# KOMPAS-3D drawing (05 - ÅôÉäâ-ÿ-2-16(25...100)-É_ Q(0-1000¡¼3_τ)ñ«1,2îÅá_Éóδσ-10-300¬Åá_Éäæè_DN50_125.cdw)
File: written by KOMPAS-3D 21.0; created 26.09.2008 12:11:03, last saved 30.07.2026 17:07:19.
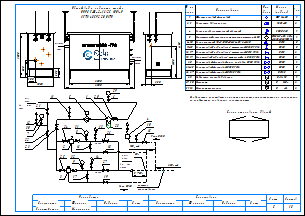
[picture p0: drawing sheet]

Sheets 1-2: A3, landscape

Document properties: Наименование: Макро:21; Автор: RaskoAdmin; Форматы листов документа: 2xA3; Полное имя файла: \\ur38nt01\Departments\КТО\КБ ПУРДГ\Заявки\Прайс-лист на типовые шкафы ГРПШ\ПУРДГ_стандарт_30_04_2026\ПУРДГ с РДСК\ПУРДГ-Ш-2-16(25...100)-Р_ Q(0-1000нм3_ч)до1,2МПа_Рвых-10-300кПа_РДСК_DN50_125.cdw

Title block, sheet 1: Наименование: Пункт учета газа / ПУГ-Ш-400-Р / ЛГТИ.485922.001ТУ; designation: ЛГТИ.03.4411141; sheet number: 1; Количество листов документа: 2; organisation: ООО "ЭЛЬСТЕР Газэлектроника"; Форматы листов документа: A3; stored path: C:\Рабочие документы\Компас\ПУГ\Схема.cdw; Разработал: Устинов; Проверил: Кошкин; Утвердил: Кошкин
Title block, sheet 2: sheet number: 2; stored path: D:\Рабочие документы\Заявки\ПУРДГ\ПУРДГ-ШУЭО-2-100-Р 4411220.cdw; designation, second copy: ЛГТИ.03.4411141-

Views: Вид 1, Вид 2
Referenced files: wcvoit.frw
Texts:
  Normal
  № на
  схеме
  Усл.
  обозн.
  Марка
  (модель)
  Кол.
  Фильтр газовый фланцевый
  ФГ 16-50
  Регулятор давления газа
  РДСК-50
  Клапан предохранительный сбросной
  КПС DN20
  Измерительный комплекс с ротационным счетчиком Ду50
  СГ-ЭК-Р-(0,2...2,0)-
  Кран кнопочный VE-РАСКО-НЗ-1,6-G1/2-М20
  DN15
  Кран шаровой "под приварку" штуцерный DN20 PN16
  DN20
  Кран шаровой "под приварку" штуцерный DN15 PN16
  Кран шаровой "под приварку" штуцерный п/п DN20 PN16
  Кран шаровой фланцевый с мех. приводом DN50 PN16
  Кран шаровой фланцевый DN50 PN16
  Кран шаровой фланцевый DN125 PN16
  DN50
  DN125
  Индикатор перепада давления
  Манометр
  Манометр-напоромер
  Delta 15
  0...     МПа
  0...     кПа
  Общий вид и габариты шкафа
  ПУРДГ-Ш-2-16(25...100)-Р
  Выход газа
  Вход газа
  logo-rasko-ge.png
  DN 1
  местное
  сопротивление
  Римп DN20
  Выход
  газа
  Р=     кПа
  Вход
  Р=       МПа
  PDI
  Схема открывания дверей
  Предприятие изготовитель может заменять комплектующие на аналогичные,
  не ухудшающие заявленных характеристик.
  Должность
  Конструктор
  Фамилия
  Подпись
  Дата
  Согласовано
  Максимкин
  Лист
  Листов
  POLYLINE_STYLE_0.18_RGB_0_0_0
  POLYLINE_STYLE_0.50_RGB_0_0_0
  POLYLINE_STYLE_0.34_RGB_0_0_0
  PHANTOM_RGB_0_0_0_SC_1_THICK_0.18
  K5LT_THIN_RGB_0_0_0_THICK_0.18
  K5LT32769_RGB_0_0_0_THICK_0.18
  K5LT12_RGB_0_0_0_SC_1_THICK_0.18
  K5LT_DASHED_RGB_0_0_0_SC_1_THICK_0.18
  ACISOTGL_RGB_0_0_0_SC_0.8_THICK_0.25
  CONTINUOUS_RGB_0_127_31_THICK_0.3
  CONTINUOUS_RGB_0_0_255_THICK_0.35
  CONTINUOUS_RGB_255_0_0_THICK_0.35
  POLYLINE_STYLE_0.25_RGB_0_0_0
  CONTINUOUS_RGB_0_0_0_THICK_0.5
  POLYLINE_STYLE_0.35_RGB_0_0_255
  CONTINUOUS_RGB_0_0_0_THICK_0.4
  CONTINUOUS_RGB_0_0_0_THICK_0.35
  НЕВИДИМАЯ_RGB_0_0_0_SC_0.3_THICK_0.25
  СONTINUOUS_RGB_0_0_0_THICK_0.25
  ОСЕВАЯ2_RGB_248_153_30_SC_0.3_THICK_0.25
  Без оформления
Dimensions and other numbers on the sheet: 1; 2, 3; 2; 4; 5; 6-10; 11-15; 16, 17; 18, 19; 20; 21-25; 26, 27; 28; 29, 30; 31, 32; 1500; 250; 300; 1050; 550; 305; 2500; 4130; 2000; 2800; 5,,,7DN 1; 7; 30; 12; 21; 22; 23; 11; 6; 29; 24; 31; 8; 16; 13; 26; 18; 10; 15; 25; 32; 9; 3; 17; 14; 27; 19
